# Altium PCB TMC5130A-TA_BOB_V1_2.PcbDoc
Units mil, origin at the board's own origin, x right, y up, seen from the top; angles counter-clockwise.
Board outline 1000 x 1100 mil, 4 copper layers (Top, GND, VM, Bottom), stack 27.719 mil thick; 26 components, 28 nets, 109 pads, 105 vias.
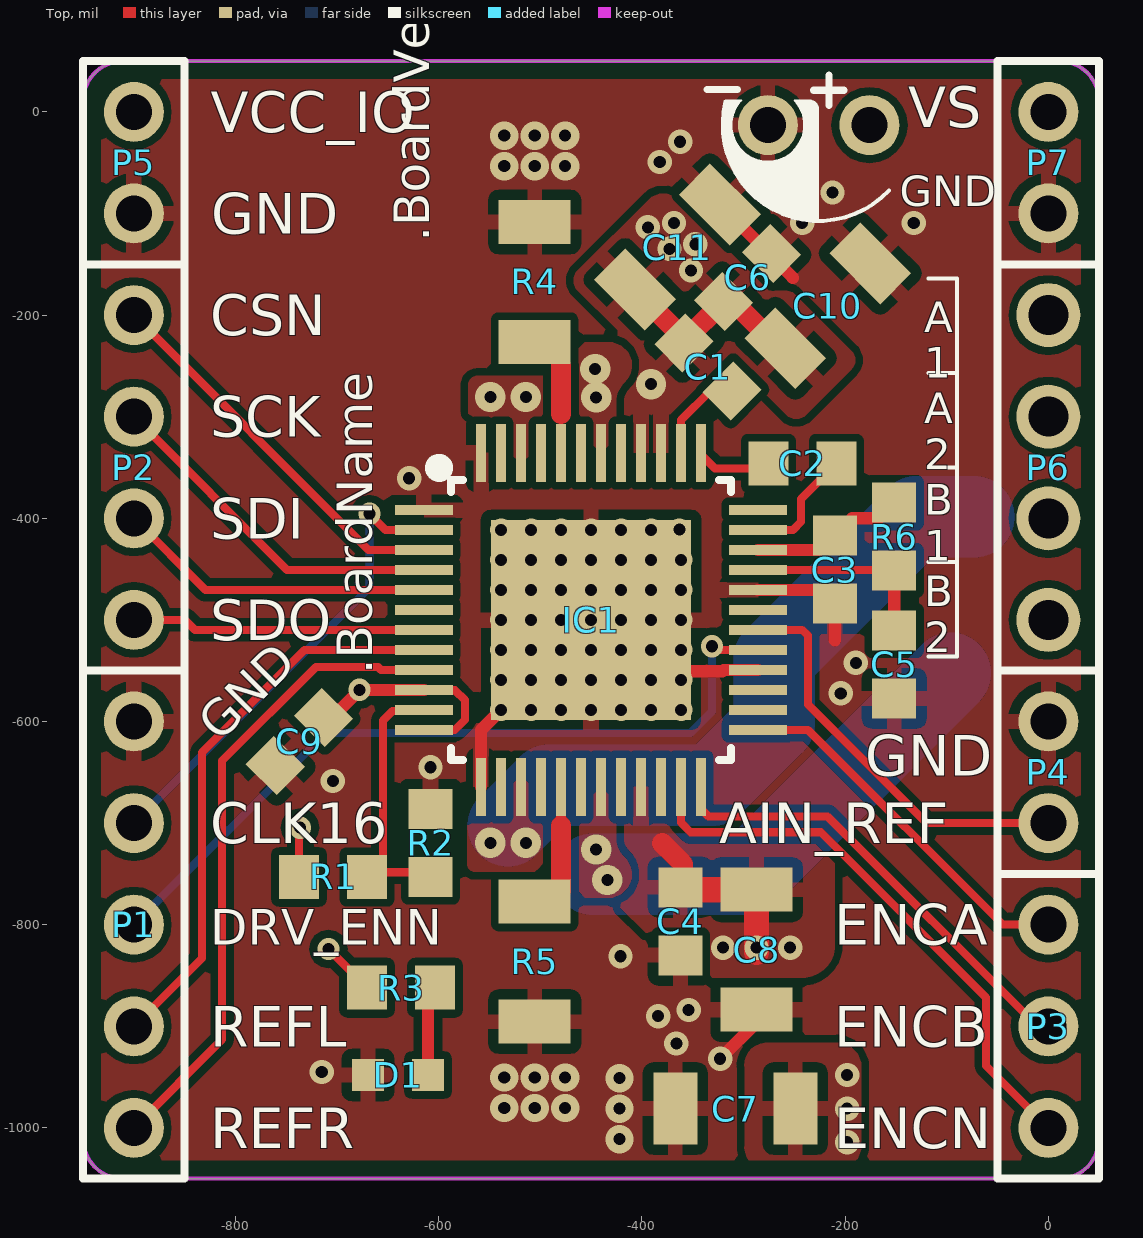
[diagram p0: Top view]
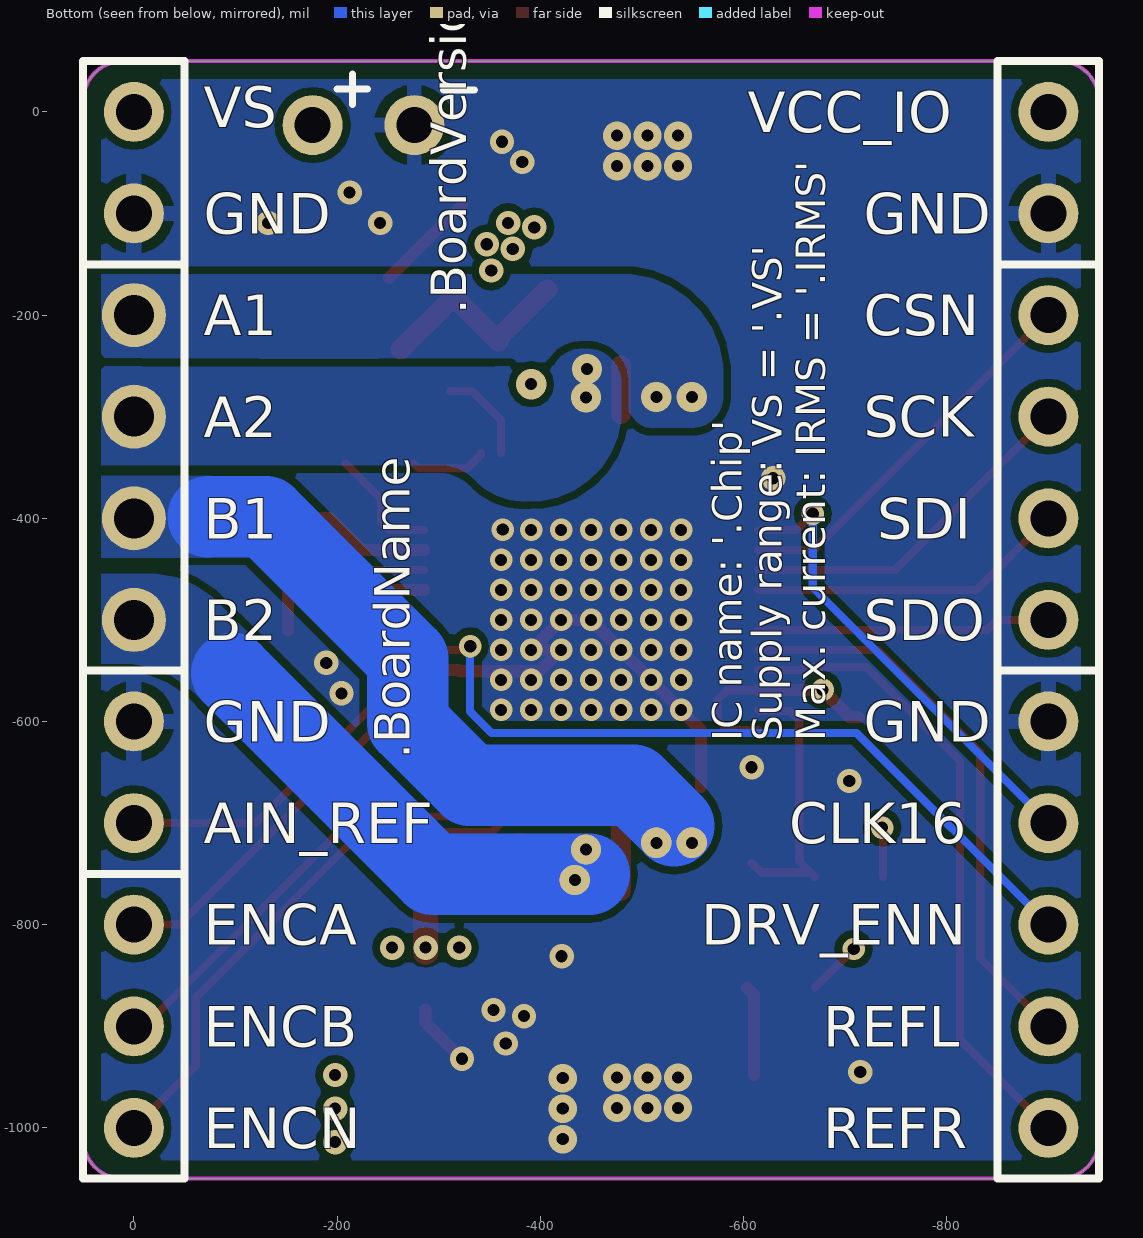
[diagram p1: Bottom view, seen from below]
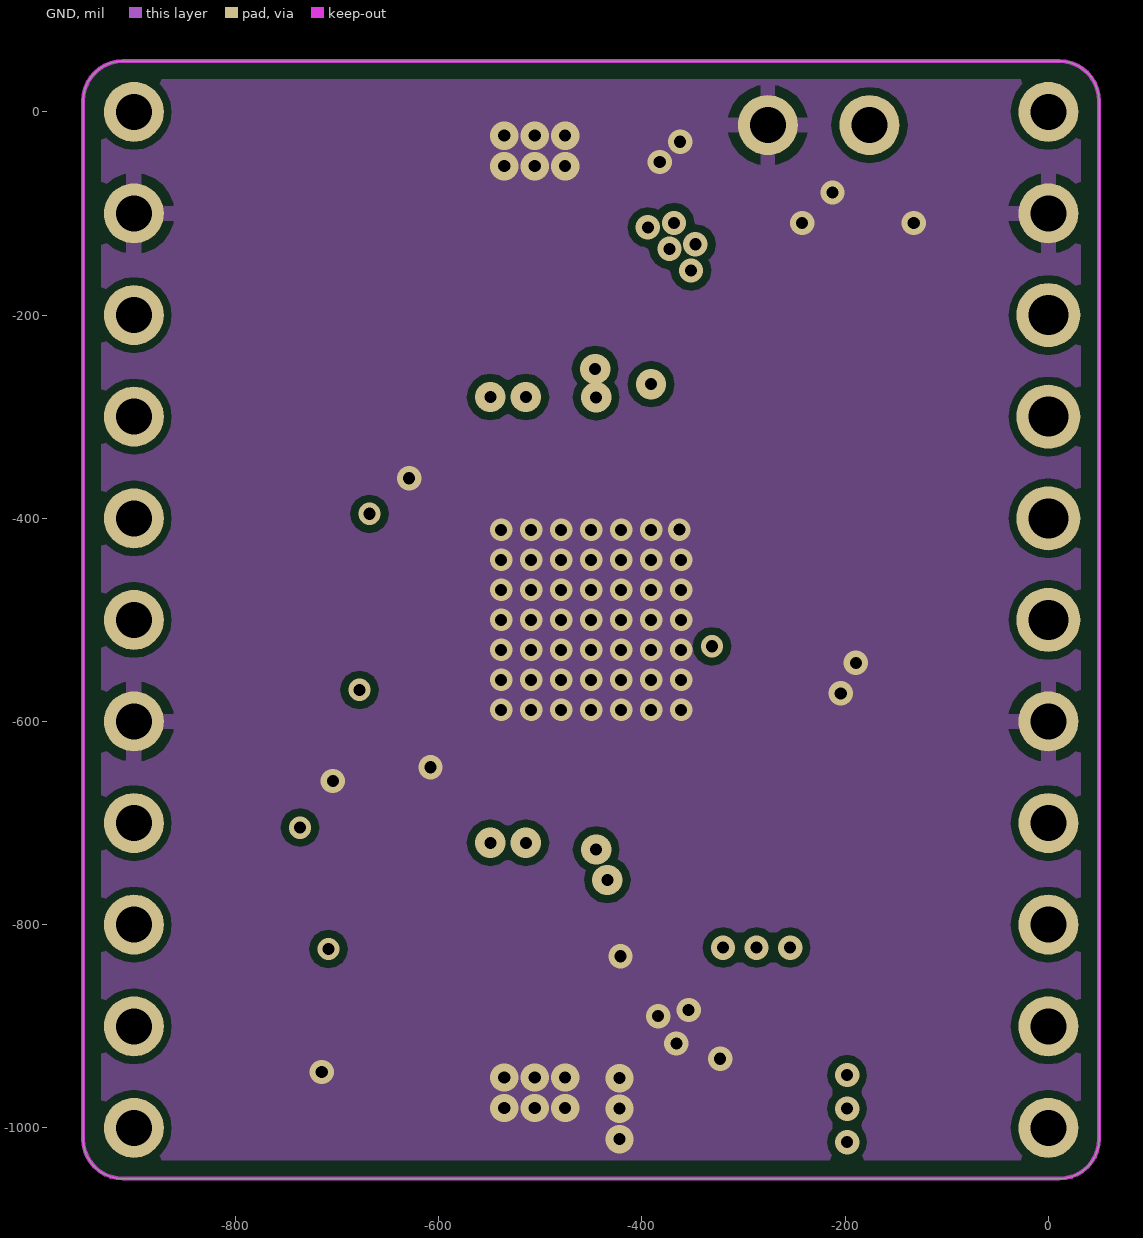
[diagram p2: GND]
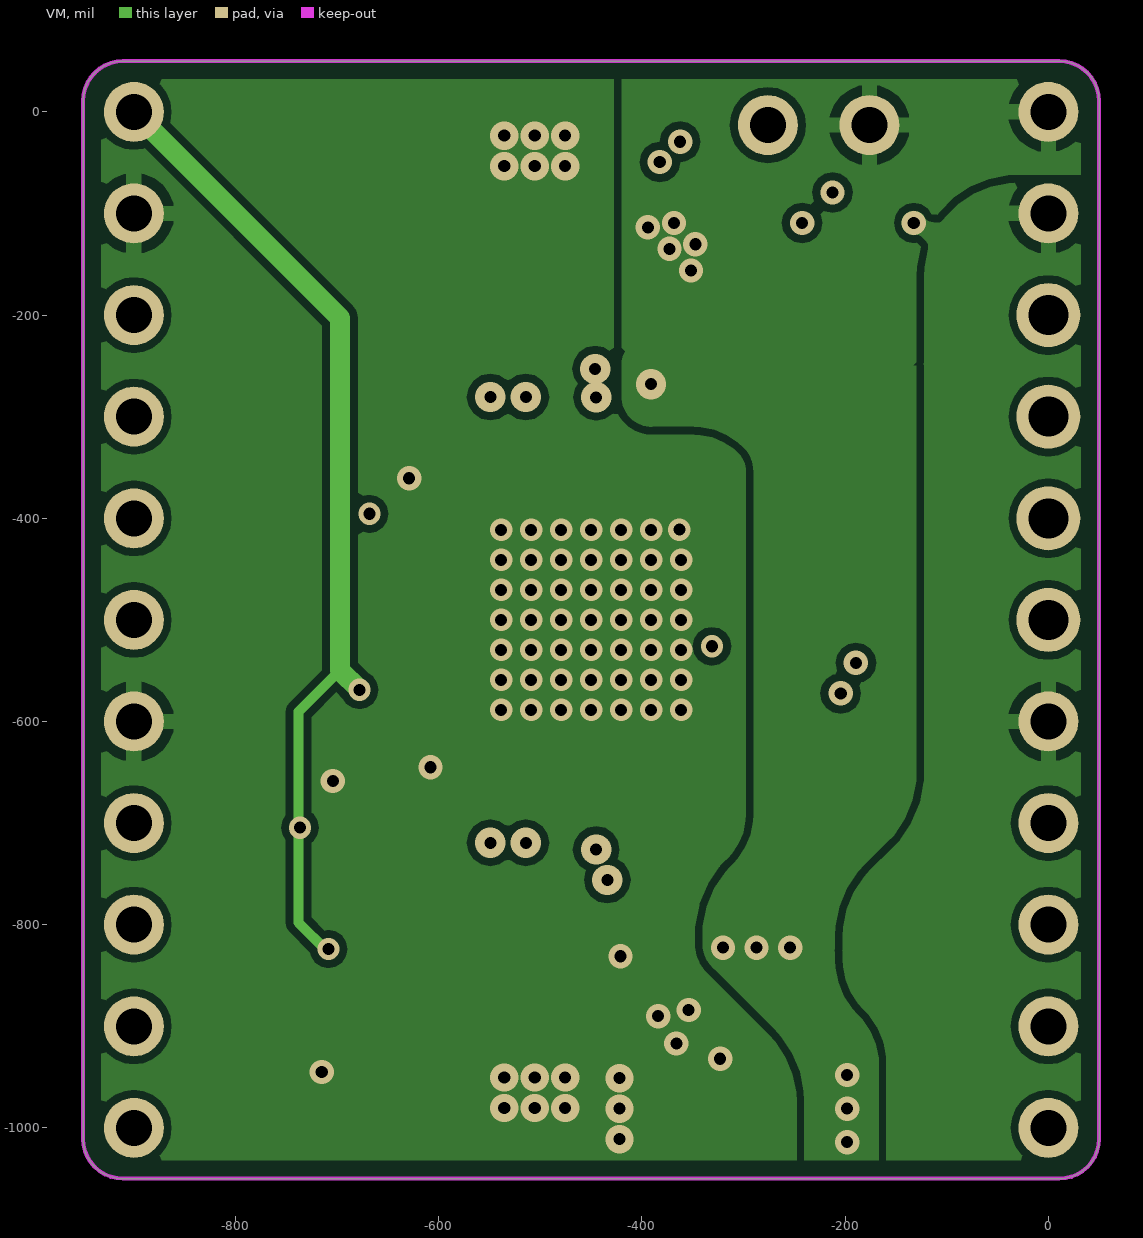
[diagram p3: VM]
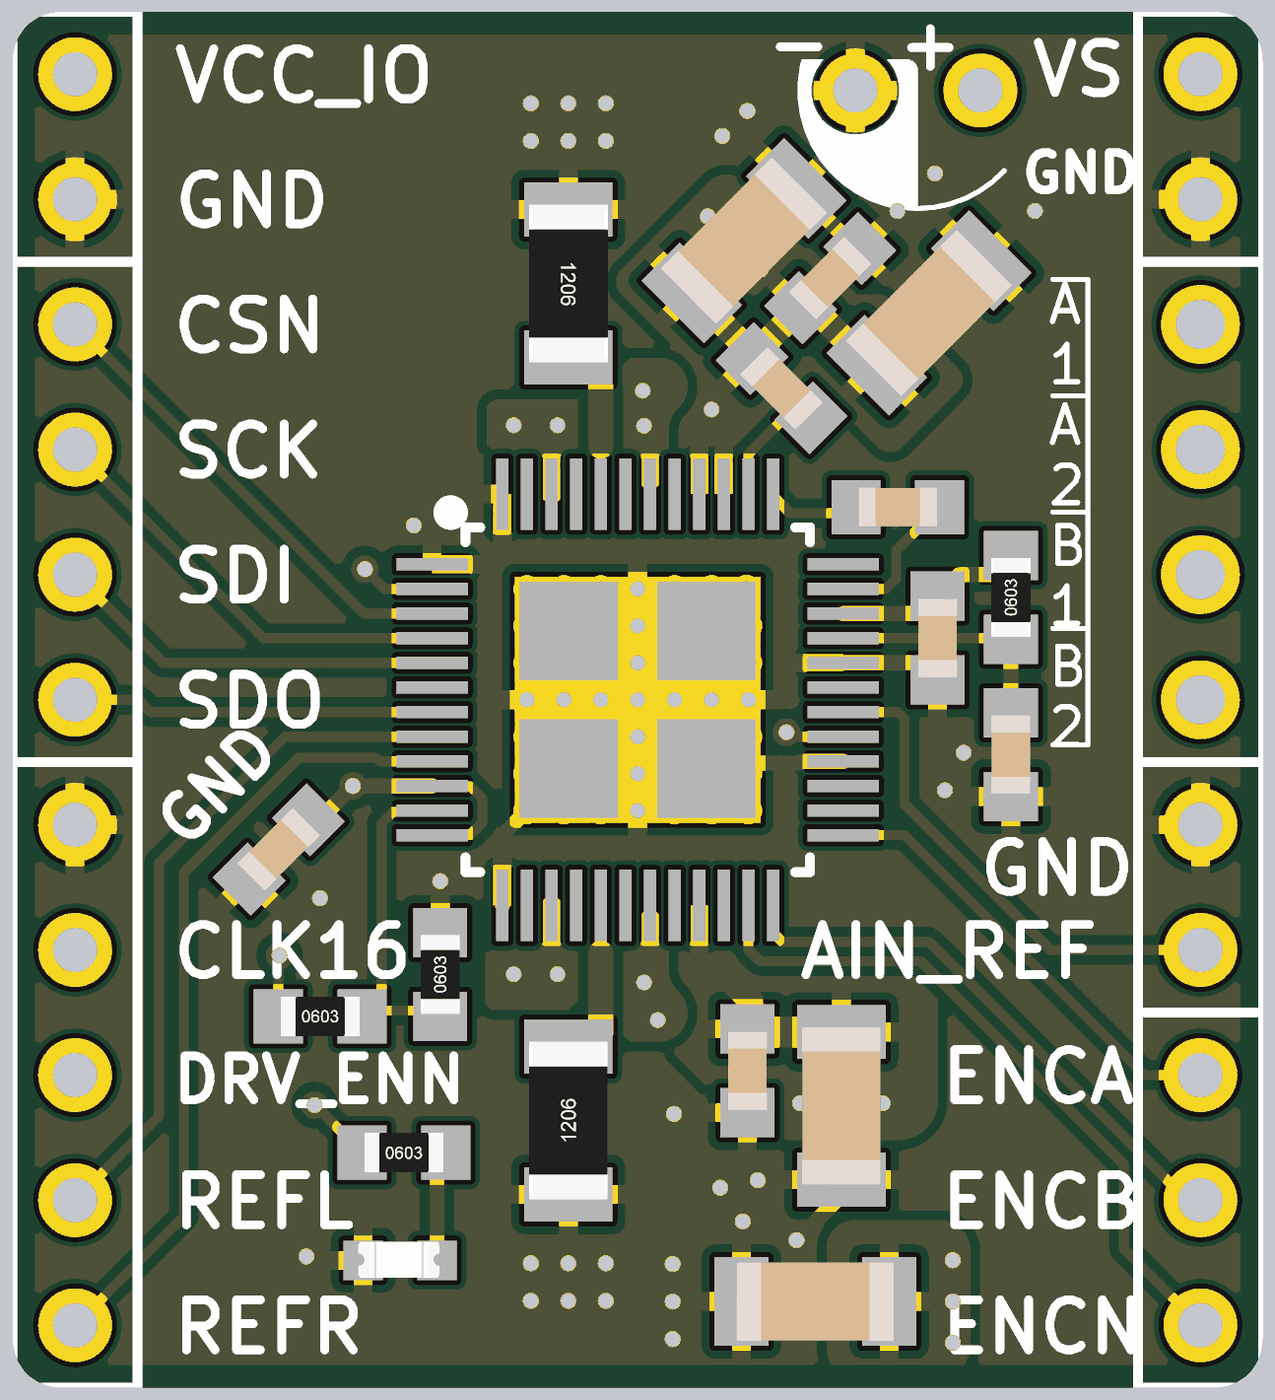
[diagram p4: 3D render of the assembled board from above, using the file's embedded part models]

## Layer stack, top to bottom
Top Solder: solder mask 0.4, Solder Resist, Dk 3.5
Top: signal copper 1.378
Dielectric 1: core 7.874, FR-4, Dk 4.8
GND: signal copper 0.689
Dielectric 2: prepreg 5, FR-4, Dk 4.2
VM: signal copper 1.4
Dielectric4: core 10, FR-4, Dk 4.2
Bottom: signal copper 1.378
Bottom Solder: solder mask 0.4, Solder Resist, Dk 3.5

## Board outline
-950,-1010.63 -950,10.63 cw(c-910.63,10.63) -910.63,50 10.63,50 cw(c10.63,10.63) 50,10.63 50,-1010.63 cw(c10.63,-1010.63) 10.63,-1050 -910.63,-1050 cw(c-910.63,-1010.63)

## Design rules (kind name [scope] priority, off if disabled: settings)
Clearance BoardOutlineClearance [OnLayer('Keep-Out Layer')] p1: gap=15.75 ignorepadtopadclearanceinfootprint=FALSE except(0: Arc-Hole Track-Hole SMDPad-Hole THPad-Hole Via-Hole Fill-Hole Poly-Hole Region-Hole Text-Hole)
Clearance "Fiducial Clearance" [HasFootprint('FIDUCIAL_40MIL')] p2: gap=26 ignorepadtopadclearanceinfootprint=FALSE except(0: Arc-Hole Track-Hole SMDPad-Hole THPad-Hole Via-Hole Fill-Hole Poly-Hole Region-Hole Text-Hole)
Clearance "Mounting Hole Clearance" [(HoleDiameter >= 110) And  IsPad  And ((PadYSize_AllLayers - HoleDiameter)  <=  1)] p3: gap=30 ignorepadtopadclearanceinfootprint=FALSE except(0: Arc-Hole Track-Hole SMDPad-Hole THPad-Hole Via-Hole Fill-Hole Poly-Hole Region-Hole Text-Hole)
Clearance [All] p4: gap=7.6 ignorepadtopadclearanceinfootprint=FALSE except(0: Arc-Hole Track-Hole SMDPad-Hole THPad-Hole Via-Hole Fill-Hole Poly-Hole Region-Hole Text-Hole)
ComponentClearance Pinheader2PinheaderClearance [InComponentClass('Pinheader') vs InComponentClass('Pinheader')] p1: gap=0 collisioncheckmode=3 verticalgap=0 showdistances=FALSE
ComponentClearance [All] p2: gap=10 collisioncheckmode=3 verticalgap=10 showdistances=FALSE
DiffPairsRouting [All] p1 off: maxlimit=10 minlimit=7.5 mostfreqgap=10 toplayer_prefgap=7.5 toplayer_minwidth=7.5 toplayer_maxwidth=7.5 toplayer_prefwidth=7.5 midlayer1_prefgap=7.5 midlayer1_minwidth=7.5 midlayer1_maxwidth=7.5 midlayer1_prefwidth=7.5 midlayer2_mingap=10 midlayer2_minwidth=15 midlayer2_maxwidth=15 midlayer2_prefwidth=15 bottomlayer_prefgap=7.5 bottomlayer_minwidth=7.5 bottomlayer_maxwidth=7.5 bottomlayer_prefwidth=7.5 maxuncoupledlength=500
HoleSize [All] p1: absolutevalues=TRUE maxlimit=100000 minlimit=11.81 maxpercent=80.000 minpercent=20.000
HoleToHoleClearance [All] p1: gap=8 allowstackedmicrovias=TRUE
MatchedLengths "SD_CARD MatchedLengths" [InNetClass('SD_CARD')] p1: tolerance=10 checknetsindiffpair=FALSE checkdiffpairvsdiffpair=TRUE checkxsignals=TRUE checkothers=TRUE
MinimumAnnularRing MinimumViaAnnualRing [All] p1: minimumring=4.92
MinimumSolderMaskSliver STM32_MinimumSolderMaskSliver [(InComponent('STM1') AND InComponent('STM2')) vs (InComponent('STM1') AND InComponent('STM2'))] p1: minsoldermaskwidth=1
MinimumSolderMaskSliver USB_HUB_MinimumSolderMaskSliver [InComponent('USB_HUB')] p2: minsoldermaskwidth=1
MinimumSolderMaskSliver [All] p3 off: minsoldermaskwidth=1.5
PasteMaskExpansion TestPadPasteMaskExpansion [HasFootprint('SMD_TP_2X2_ROUND')] p1: expansion=-78.74
PasteMaskExpansion [All] p2: expansion=0
PolygonConnect MotorpowerOutput_VM_PolygonConnect [InNetClass('MotorPowerOut')] p1: connectstyle=Direct reliefconductorwidth=70 reliefentries=4 polygonreliefangle="90 Angle" airgapwidth=10
PolygonConnect ThermalVias [IsVia] p2: connectstyle=Direct reliefconductorwidth=10 reliefentries=4 polygonreliefangle="90 Angle" airgapwidth=10
PolygonConnect MotorOutputConStyle [InNetClass('MotorOutput')] p3: connectstyle=Direct reliefconductorwidth=10 reliefentries=4 polygonreliefangle="90 Angle" airgapwidth=10
PolygonConnect [All] p4: connectstyle=Relief reliefconductorwidth=15 reliefentries=4 polygonreliefangle="90 Angle" airgapwidth=10
RoutingVias [All] p1: holewidth=12 width=22 viastyle="Through Hole" minholewidth=12 minwidth=22 maxholewidth=12 maxwidth=50
ShortCircuit [All] p1 off: allowed=FALSE
SilkToBoardRegionClearance [All] p1 off:
SilkToSilkClearance [All] p1 off: silktosilkclearance=10
SilkToSolderMaskClearance [IsPad] p1 off: minsilkscreentomaskgap=10 clearancetoexposedcopper=TRUE
SolderMaskExpansion FiducialSolderMaskExpansion [HasFootprint('FIDUCIAL_40MIL')] p1: expansion=26
SolderMaskExpansion [All] p2: expansion=4
UnRoutedNet [All] p1 off:
Width VIN_Width [InNetClass('PWR_VIN')] p1: maxlimit=300 minlimit=200 preferedwidth=210
Width Other_Width [All] p2: maxlimit=100000 minlimit=8 preferedwidth=11.81 minimp=50.000000 maximp=50.000000 favimp=50.000000
19 further rules are at their usual default settings.

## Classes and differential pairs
net class C1_Nets: +VS NetC1_2
net class C2_Nets: NetC2_1 NetC2_2
net class C3_Nets: GND VCC
net class C4_Nets: +VS GND
net class C5_Nets: 5V_OUT GND
net class C6_Nets: +VS GND
net class C7_Nets: +VS GND
net class C8_Nets: +VS GND
net class C9_Nets: GND VCC_IO
net class C10_Nets: +VS GND
net class C11_Nets: +VS GND
net class C17_Nets: +VS GND
net class D1_Nets: GND NetD1_1
net class IC1_Nets: 5V_OUT +VS AIN_REF CLK16 CSN DRV_ENN ENCA ENCB ENCN GND NetC1_2 NetC2_1 NetC2_2 NetIC1_17 NetIC1_26 NetIC1_27 NetIC1_44 OA1 OA2 OB1 OB2 REFL REFR SCK SD_MODE SDI SDO VCC VCC_IO
net class MotorPowerOut: OA1 OA2 OB1 OB2
net class P1_Nets: CLK16 DRV_ENN GND REFL REFR
net class P2_Nets: CSN SCK SDI SDO
net class P3_Nets: ENCA ENCB ENCN
net class P4_Nets: AIN_REF GND
net class P5_Nets: GND VCC_IO
net class P6_Nets: OA1 OA2 OB1 OB2
net class P7_Nets: +VS GND
net class R1_Nets: SD_MODE VCC_IO
net class R2_Nets: GND SD_MODE
net class R3_Nets: NetD1_1 VCC_IO
net class R4_Nets: GND NetIC1_44
net class R5_Nets: GND NetIC1_17
net class R6_Nets: 5V_OUT VCC

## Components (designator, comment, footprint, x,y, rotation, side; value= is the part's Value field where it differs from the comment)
C1 "100nF" C0603 -335,-251 r315 top
C2 "22nF" C0603 -242,-346 r180 top
C3 "470nF" C0603 -210.16,-450.63 r270 top
C4 "100nF" C0603 -362.16,-796.63 r270 top
C5 "4.7uF" C0603 -151.63,-543.84 r270 top
C6 "100nF" C0603 -296,-163 r45 top
C7 "10uF/35V/10%" C1206 -308,-981 r0 top
C8 "10uF/35V/10%" C1206 -287.16,-824.63 r90 top
C9 "100nF" C0603 -737.16,-619.63 r225 top
C10 "10uF/35V/10%" C1206 -217.08,-190.84 r225 top
C11 "10uF/35V/10%" C1206 -365,-133 r225 top
D1 "LED, Blue, SMD, 20mA, 2.8V, 465 nm" LED_0603 -640,-948 r180 top
IC1 "TMC5130A-TA" TMC5130_TQFP48-EP_0.5_7.0X7.0 -450,-500 r270 top
P1 "MISC" 5_PIN_THT -900,-1000 r0 top
P2 "SPI" 4_PIN_THT -900,-200 r180 top
P3 "ENC" 3_PIN_THT 0,-1000 r0 top
P4 "AIN" 2_PIN_THT 0,-700 r0 top
P5 "VCC_IO" 2_PIN_THT -900,-100 r0 top
P6 "MAB" 4_PIN_THT_1mm_hole 0,-200 r180 top
P7 "VM" 2_PIN_THT 0,-100 r0 top
R1 "0R" R0603 -704,-753 r0 top
R2 "0R" R0603 -608,-719.54 r90 top
R3 "1k" R0603 -637,-862 r0 top
R4 "0.15R / 0.5W / 1%" R1206 -505.53,-167.37 r270 top
R5 "0.15R / 0.5W / 1%" R1206 -505.53,-836.37 r90 top
R6 "2R2/1%/" R0603 -151.63,-418.17 r90 top

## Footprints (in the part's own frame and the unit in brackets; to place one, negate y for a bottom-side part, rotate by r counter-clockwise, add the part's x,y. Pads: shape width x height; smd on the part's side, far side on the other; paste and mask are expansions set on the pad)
2_PIN_THT [mm]
  round 1.5 hole 0.9: 1(0,0) 2(0,2.54)
  silkscreen extent -1.27,-1.27 1.27,3.81
3_PIN_THT [mm]
  round 1.5 hole 0.9: 1(0,0) 2(0,2.54) 3(0,5.08)
  silkscreen extent -1.27,-1.27 1.27,6.35
4_PIN_THT [mm]
  round 1.5 hole 0.9: 1(0,0) 2(0,2.54) 3(0,5.08) 4(0,7.62)
  silkscreen extent -1.27,-1.27 1.27,8.89
4_PIN_THT_1mm_hole [mm]
  round 1.6 hole 1: 1(0,0) 2(0,2.54) 3(0,5.08) 4(0,7.62)
  silkscreen extent -1.27,-1.27 1.27,8.89
5_PIN_THT [mm]
  round 1.5 hole 0.9: 1(0,0) 2(0,2.54) 3(0,5.08) 4(0,7.62) 5(0,10.16)
  silkscreen extent -1.27,-1.27 1.27,11.43
C0603 [mm] "0603 ceramic capacitor"
  rect 1x1.1 smd: 1(-0.85,0) 2(0.85,0)
  body extent -0.8,-0.4 0.8,0.4, height 0.8
C1206 [mm] "1206 ceramic capacitor"
  rect 1.1x1.8 smd: 1(-1.5,0) 2(1.5,0)
  body extent -1.6,-0.8 1.6,0.8, height 0.76
LED_0603 [mm]
  rect 0.8x0.8 smd: 1(-0.75,0) 2(0.75,0)
  body extent -0.8,-0.38 0.85,0.35, height 0.68
R0603 [mm] "0603 resistor"
  rect 1x1.1 smd: 1(-0.85,0) 2(0.85,0)
  body extent -0.8,-0.4 0.8,0.4, height 0.45
R1206 [mm] "1206 resistor"
  rect 1.1x1.8 smd: 1(-1.5,0) 2(1.5,0)
  body extent -1.6,-0.8 1.6,0.8, height 0.6
TMC5130_TQFP48-EP_0.5_7.0X7.0 [mm]
  rect 0.25x1.45 smd: 1(-2.75,-4.175) 2(-2.25,-4.175) 3(-1.75,-4.175) 4(-1.25,-4.175) 5(-0.75,-4.175) 6(-0.25,-4.175) 7(0.25,-4.175) 8(0.75,-4.175) 9(1.25,-4.175) 10(1.75,-4.175) 11(2.25,-4.175) 12(2.75,-4.175) 25(2.75,4.175) 26(2.25,4.175) 27(1.75,4.175) 28(1.25,4.175) 29(0.75,4.175) 30(0.25,4.175) 31(-0.25,4.175) 32(-0.75,4.175) 33(-1.25,4.175) 34(-1.75,4.175) 35(-2.25,4.175) 36(-2.75,4.175)
  rect 1.45x0.25 smd: 13(4.175,-2.75) 14(4.175,-2.25) 15(4.175,-1.75) 16(4.175,-1.25) 17(4.175,-0.75) 18(4.175,-0.25) 19(4.175,0.25) 20(4.175,0.75) 21(4.175,1.25) 22(4.175,1.75) 23(4.175,2.25) 24(4.175,2.75) 37(-4.175,2.75) 38(-4.175,2.25) 39(-4.175,1.75) 40(-4.175,1.25) 41(-4.175,0.75) 42(-4.175,0.25) 43(-4.175,-0.25) 44(-4.175,-0.75) 45(-4.175,-1.25) 46(-4.175,-1.75) 47(-4.175,-2.25) 48(-4.175,-2.75)
  rrect0% 5x5 smd paste-254: 49(0,0)
  silkscreen extent -3.9,-3.9 3.5,3.5, body extent -3.5,-3.5 3.5,3.5, height 1

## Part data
C1: library part Capacitor, "Ceramic capacitor", MPN=MC0603F104M500CT, Voltage rating=50V
C2: library part Capacitor, "Ceramic capacitor", MPN=MC0603B223K500CT, Voltage rating=50V
C3: library part Capacitor, "Ceramic capacitor", MPN=MC0603X474K160CT, Voltage rating=16V
C4 C6 C9: library part Capacitor, "Ceramic capacitor", Manufacturer=Multicomp, MPN=MC0603F104M500CT, Voltage rating=50V
C5: library part Capacitor, "Ceramic capacitor", MPN=MC0603X475K100CT, Voltage rating=10V
C7 C8 C10 C11: library part Capacitor, "Ceramic capacitor", Capacitance=10uF, MPN=GRM31CC8YA106KA12L, VoltageRating=35V
D1: Colour=Blue, Current rating=20mA, MPN=LTST-C191TBKT-5A
IC1: "High voltage(up to 46V) controller for two-phase bipolar stepper motor, with SPI, Step/Dir, UART, TQFP48-EP(7x7)", Manufacturer=TRINAMIC
P1: library part "Header 5", "Header, 5-Pin"
P2: library part "Header 4", "Header, 4-Pin"
P3: library part "Header 3", "Header, 3-Pin"
P4 P5 P7: library part "Header 2", "Header, 2-Pin"
P6: library part "Wire-To-Board Connector, 2.5 mm, 4 Contacts, Header, EH Series, Through Hole, 1 Rows", "Wire-To-Board Connector, 2.5 mm, 4 Contacts, Header, EH Series, Through Hole, 1 Rows", MPN=B4B-EH-A
R1 R2: library part "0 ohm, 0603 [1608 Metric], 100 mW, MCWR Series", "SMD Chip Resistor, Thick Film, 0 ohm, 0603 [1608 Metric], 100 mW, MCWR Series", MPN="MCWR06X000 PTL", PowerRating=100mW, Temp coefficient=*ppm
R3: library part "1 kohm, 50 V, 0603 [1608 Metric], 63 mW, ± 1%, MC Series", "1 kohm, 50 V, 0603 [1608 Metric], 63 mW, ± 1%, MC Series", MPN=MC0063W060311K, PowerRating=63mW, Temp coefficient=*ppm, VoltageRating=50V
R4 R5: library part "0.15 Ohm ±1% 0.5W, 1/2W Chip Resistor 1206 (3216 Metric) Automotive AEC-Q200, Current Sense Thick Film", "0.15 Ohm ±1% 0.5W, 1/2W Chip Resistor 1206 (3216 Metric) Automotive AEC-Q200, Current Sense Thick Film", MPN=ERJ-8BSFR15V, PowerRating=0.5W, Resistance=0.15R, Temp coefficient=*ppm
R6: library part Resistor, "Resistor", MPN=MC0063W060312R2, Power rating=*mW, Resistance=2R2, Temp coefficient=*ppm, Voltage rating=*V

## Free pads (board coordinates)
  round 59.06 hole 35.43: 1(-176,-13) 2(-276,-13)

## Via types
v1: diameter 22, hole 12, Top to Bottom, tented both sides, 54 vias
v2: diameter 24, hole 12, Top to Bottom, tented both sides, 27 vias
v3: diameter 28, hole 12, Top to Bottom, tented both sides, 15 vias
v4: diameter 29.81, hole 11.81, Top to Bottom, tented both sides, 9 vias

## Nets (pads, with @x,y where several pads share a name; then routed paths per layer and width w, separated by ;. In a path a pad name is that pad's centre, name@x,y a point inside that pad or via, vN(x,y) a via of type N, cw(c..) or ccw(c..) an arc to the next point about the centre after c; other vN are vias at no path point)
5V_OUT: C5.1 IC1.33 R6.1 | length 180.4
  Top w8: IC1.33 R6.1@-164,-450.79
  Top w12: C5.1 R6.1
+VS: C1.1 C4.1 C6.1 C7.2 C8.2 C10.2 C11.2 IC1.21 IC1.39 IC1.40 P7.2 pad.1 | length 393.2
  Top w8: v2(-287.16,-822.52) v2@-286.16,-822.52
  Top w12: C1.1 -358.66,-225.66 C1.1@-358.66,-222.85
  Top w20: C11.2 C1.1@-358.66,-222.85 ; -380,-720 -359.75,-740.25 C4.1@-359.75,-765.57 ; C1.1@-358.66,-225.66 C6.1 -309.85,-186.66 C10.2@-262.76,-233.76
  Top w25: C4.1@-359.75,-765.57 C8.2 v2@-287.16,-827.16
  other v2: -198.06,-1014 -198.06,-981 -198.06,-948 -320.16,-822.52 -254.16,-822.52 -351.65,-156.08 -372.87,-134.87 -347.34,-130.34 -394.08,-113.65 -368.34,-109.34
  other v4: -391,-268
AIN_REF: IC1.30 P4.1 | length 404.2
  Top w8: IC1.30 -242.15,-509.84 -236.62,-515.38 -236.62,-583.38 -120,-700 P4.1
CLK16: IC1.2 P1.4 | length 460.7
  Top w8: v1(-668.16,-395.63) -652.37,-411.42 IC1.2
  Bottom w8: P1.4 -668.16,-468.16 v1(-668.16,-395.63)
CSN: IC1.3 P2.1 | length 381.4
  Top w8: P2.1 -668.9,-431.1 IC1.3
DRV_ENN: IC1.29 P1.3 | length 767.4
  Top w8: v1(-331,-526) ccw(c-327.47,-526) -327.47,-529.53 IC1.29
  Bottom w8: P1.3 -711.18,-611.18 -352.06,-611.18 -331,-590.13 v1(-331,-526)
ENCA: IC1.25 P3.3 | length 365
  Top w8: IC1.25 -236.52,-608.27 -44.79,-800 P3.3
ENCB: IC1.24 P3.2 | length 452.2
  Top w8: IC1.24 -341.73,-686.27 -334.6,-693.4 -217.33,-693.4 -10.73,-900 P3.2
ENCN: IC1.23 P3.1 | length 560.4
  Top w8: IC1.23 -361.42,-699.58 -352,-709 -223.79,-709 -61.16,-871.63 -61.16,-938.84 P3.1
GND: C3.2 C4.2 C5.2 C6.2 C7.1 C8.1 C9.2 C10.1 C11.1 D1.2 IC1.1 IC1.13 IC1.28 IC1.32 IC1.48 IC1.49 P1.5 P4.2 P5.1 P7.1 pad.2 R2.2 R4.1 R5.1 | length 736.4
  Top w12: IC1.13 -558.27,-608.27 v1(-538.58,-588.58) v1(-509.06,-559.06) v1(-479.53,-529.53) v1(-450,-500) v1(-420.47,-500) v1(-390.94,-529.53) v1(-420.47,-529.53) -399.4,-550.6 -320.81,-550.6 -319.42,-549.21 IC1.28 ; C11.1 -251.43,-163.05 -251.43,-163.47 ; v2(-323,-932) -287.16,-896.16 C8.1 ; IC1.32 -223.78,-470.47 C3.2 -210.16,-519.84 -210,-520
  other v1: -509.06,-588.58 -479.53,-588.58 -450,-588.58 -420.47,-588.58 -390.94,-588.58 -361.42,-588.58 -538.58,-559.06 -479.53,-559.06 -450,-559.06 -420.47,-559.06 -390.94,-559.06 -361.42,-559.06 -538.58,-529.53 -509.06,-529.53 -450,-529.53 -361.42,-529.53 -538.58,-500 -509.06,-500 -479.53,-500 -390.94,-500 -361.42,-500 -538.58,-470.47 -509.06,-470.47 -479.53,-470.47 -450,-470.47 -420.47,-470.47 -390.94,-470.47 -361.42,-470.47 -538.58,-440.94 -509.06,-440.94 -479.53,-440.94 -450,-440.94 -420.47,-440.94 -390.94,-440.94 -361.42,-440.94 -538.58,-411.42 -509.06,-411.42 -479.53,-411.42 -450,-411.42 -420.47,-411.42 -390.94,-411.42 -363.11,-411.17
  other v2: -715,-945 -366,-917 -384,-890 -354,-884 -421,-831 -704.16,-658.63 -608,-645 -204.34,-572.34 -189.34,-542.34 -629.16,-360.63 -242.34,-109.34 -132.34,-109.34 -212.34,-79.34 -382.34,-49.34 -362.34,-29.34
  other v3: -422.06,-1011 -535.53,-980.43 -505.53,-980.43 -475.53,-980.43 -422.06,-981 -535.53,-950.43 -505.53,-950.43 -475.53,-950.43 -422.06,-951 -535.53,-53.32 -505.53,-53.32 -475.53,-53.32 -535.53,-23.32 -505.53,-23.32 -475.53,-23.32
NetC1_2: C1.2 IC1.38 | length 94.2
  Top w8: IC1.38 -361.42,-303.42 -332.66,-274.66 C1.2
NetC2_1: C2.1 IC1.35 | length 117.4
  Top w8: IC1.35 -251.42,-411.42 -243.41,-403.41 -243.41,-380.88 C2.1
NetC2_2: C2.2 IC1.37 | length 75.7
  Top w8: IC1.37 -341.73,-337.27 -328,-351 -280.46,-351 C2.2
NetD1_1: D1.1 R3.2 | length 88.9
  Top w12: D1.1 -610.47,-868.94 R3.2
NetIC1_17: IC1.17 R5.2 | length 100.2
  Top w10: -479.53,-700.78 IC1.17
  Top w20: R5.2@-479.53,-766.47 -479.53,-702.68
NetIC1_44: IC1.44 R4.2 | length 47.4
  Top w20: -479.53,-297.37 -479.53,-250
OA1: IC1.46 P6.1
  other v4: -549.21,-280.63 -514.21,-280.63
OA2: IC1.42 P6.2
  other v4: -445,-281 -446,-253
OB1: IC1.15 P6.3 | length 621.7
  Bottom w80: -531.71,-702.73 -491.76,-662.78 -330.68,-662.78 -269.6,-601.7 -269.6,-538.31 -129.66,-398.37 -73.21,-398.37
  other v4: -549.21,-719.37 -514.21,-719.37
OB2: IC1.19 P6.4 | length 434
  Bottom w80: -448.21,-750.38 -294.23,-750.38 -96.21,-552.37
  other v4: -434,-756 -445,-726
REFL: IC1.8 P1.2 | length 557.8
  Top w8: P1.2 -833.03,-833.03 -833.03,-630.4 -732.16,-529.53 IC1.8
REFR: IC1.9 P1.1 | length 635.6
  Top w8: P1.1 -813.16,-913.16 -813.16,-638.63 -720.83,-546.3 -659.54,-546.3 -656.63,-549.21 IC1.9
SCK: IC1.4 P2.2 | length 348.1
  Top w8: P2.2 -749.21,-450.79 IC1.4
SD_MODE: IC1.11 R1.2 R2.1 | length 267
  Top w8: R1.2 R1.2@-665.9,-748.36 ; IC1.11 -615.29,-589.5 -645.48,-589.5 -654.85,-598.88 -654.85,-737.31 R1.2@-665.9,-748.36 ; R2.1@-608,-739.28 -617.08,-748.36 R1.2@-665.9,-748.36
SDI: IC1.5 P2.3 | length 314.8
  Top w8: P2.3 -829.53,-470.47 IC1.5
SDO: IC1.7 P2.4 | length 289.7
  Top w8: P2.4 -849.63,-500 -839.79,-509.84 IC1.7
VCC: C3.1 IC1.34 R6.2 | length 153.2
  Top w12: IC1.34 -224.09,-431.1 C3.1 -192.99,-400 -166.93,-400 R6.2
VCC_IO: C9.1 IC1.10 IC1.12 P5.2 R1.1 R3.1 | length 1286.3
  Top w8: R1.1 -737.46,-705.46 v1(-736.46,-704.46) ; v1(-708.46,-824) R3.1 ; IC1.12 -584.19,-608.27 -574.23,-598.31 -574.23,-578.86 -583.77,-569.31 -613.96,-569.31 IC1.10
  Top w12: C9.1 -704.76,-595.97 v1@-677.79,-569 ; v1@-677.69,-568.9 IC1.10
  VM w10: v1@-710.23,-825.77 -738,-798 -738,-590.47 -697.16,-549.63
  VM w20: P5.2 -697.16,-202.84 -697.16,-549.63 v1(-677.89,-568.9)
pads on no net: IC1.6 IC1.14 IC1.16 IC1.18 IC1.20 IC1.22 IC1.26 IC1.27 IC1.31 IC1.36 IC1.41 IC1.43 IC1.45 IC1.47

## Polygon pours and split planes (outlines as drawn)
OA1 on Top "OA1" (solid, pour order 11): -518.9,-342.52 ccw(c-518.9,-332.68) -509.06,-332.68 -509.06,-307.09 cw(c-505.12,-307.09) -505.12,-303.15 -497.25,-303.15 ccw(c-497.25,-299.22) -493.31,-299.22 -493.31,-295.28 -493.31,-263.78 ccw(c-497.25,-263.78) -497.25,-259.85 -561.76,-259.85 ccw(c-561.76,-268.93) -570.84,-268.93 -570.84,-295.28 ccw(c-562.07,-294.38) -561.17,-303.15 -536.62,-303.15 -532.68,-303.15 cw(c-532.68,-307.09) -528.74,-307.09 -528.74,-332.68 ccw(c-518.9,-332.68)
OB1 on Top "OB1" (solid, pour order 10): -518.9,-657.48 cw(c-518.9,-667.33) -509.06,-667.33 -509.06,-692.92 ccw(c-505.12,-692.92) -505.12,-696.85 -497.25,-696.85 cw(c-497.25,-700.79) -493.31,-700.79 -493.31,-724.41 cw(c-521.83,-724.41) -501.66,-744.58 -505.12,-748.03 -540.56,-748.03 -564.18,-748.03 cw(c-564.18,-740.16) -572.05,-740.16 -572.05,-704.73 cw(c-564.18,-704.73) -564.18,-696.85 -532.72,-696.85 -532.72,-696.61 -532.44,-696.61 ccw(c-532.44,-692.92) -528.74,-692.92 -528.74,-667.33 cw(c-518.9,-667.33) -518.9,-657.48
OA2 on Top "TOP_OA2" (solid, pour order 12): -440.16,-335.63 -455.91,-319.88 -455.91,-312.99 -479.53,-289.37 -479.53,-250 -456.16,-226.63 -443.16,-226.63 -433.16,-226.63 cw(c-433.16,-249.63) -410.16,-249.63 cw(c-434.3,-249.63) -417.23,-266.7 -418.16,-267.63 ccw(c-401.26,-284.53) -425.16,-284.53 -425.16,-285.63 -425.16,-320.63 -440.16,-335.63
OB2 on Top "TOP_OA2" (solid, pour order 13): -440.16,-664.37 -455.91,-680.12 -455.91,-687.01 -479.53,-710.63 -479.53,-750 -456.16,-773.37 -443.16,-773.37 -433.16,-773.37 ccw(c-433.16,-750.37) -410.16,-750.37 ccw(c-434.3,-750.37) -417.23,-733.3 -418.16,-732.37 cw(c-401.26,-715.47) -425.16,-715.47 -425.16,-714.37 -425.16,-679.37 -440.16,-664.37
GND on Top "TOP_GND" (solid, pour order 19): -950,-1010.63 ccw(c-910.63,-1010.63) -910.63,-1050 10.63,-1050 ccw(c10.63,-1010.63) 50,-1010.63 50,10.63 ccw(c10.63,10.63) 10.63,50 -910.63,50 ccw(c-910.63,10.63) -950,10.63
+VS on Top "TOP_VM" (solid, pour order 14): -420.47,-664.37 -445,-688.9 -445,-719 -445,-759.19 -401.16,-803.04 -352.16,-852.03 -241.72,-852.03 ccw(c-241.72,-820.31) -210,-820.31 -210,-800 -210,-739.51 -212.06,-737.46 -239.48,-710.03 -334.33,-710.03 -335.44,-710.03 -381.1,-664.37
+VS on Top "+VS_L01_P006" (solid, pour order 6): -274.94,-1041 -208.95,-1041 ccw(c-208.94,-1016) -183.94,-1016 -183.94,-941 ccw(c-208.94,-941) -208.95,-916 -276.57,-916 ccw(c-276.58,-938.51) -298.94,-941 -298.95,-1017 ccw(c-276.55,-1018.6)
+VS on Top "+VS_L01_P015" (solid, pour order 15): -424,-336.63 -424,-215 -463,-176 cw(c-453,-166) -463,-156 -393.25,-86.25 cw(c-379,-100.5) -364.75,-86.25 -274.99,-176.01 -252.99,-176.01 -194,-235 cw(c-203.49,-244.5) -194,-254 -238,-298 cw(c-248,-288) -258,-298 -298,-258 -316,-258 -359.42,-301.42 -359.42,-336.63
GND on GND "TOP_GND" (solid, pour order 18): -950,-1010.63 ccw(c-910.63,-1010.63) -910.63,-1050 10.63,-1050 ccw(c10.63,-1010.63) 50,-1010.63 50,10.63 ccw(c10.63,10.63) 10.63,50 -910.63,50 ccw(c-910.63,10.63) -950,10.63
GND on Bottom "TOP_GND" (solid, pour order 17): -950,-1010.63 ccw(c-910.63,-1010.63) -910.63,-1050 10.63,-1050 ccw(c10.63,-1010.63) 50,-1010.63 50,10.63 ccw(c10.63,10.63) 10.63,50 -910.63,50 ccw(c-910.63,10.63) -950,10.63
OA2 on Bottom "OA2_L04_P000" (solid, pour order 0): -446,-233.01 ccw(c-446.01,-266.52) -479.52,-266.52 -479.52,-294.48 ccw(c-391,-294.48) -391,-383 ccw(c-385.09,-313.04) -339.8,-366.69 cw(c-300.6,-397.54) -306.5,-348 50,-348 50,-249.77 cw(c-181.85,24817.03) -413.71,-249.77 ccw(c-440.41,-263.13) -437.42,-233.43 ccw(c-445.79,-315.62)
OA1 on Bottom "OA1_L04_P003" (solid, pour order 3): -482.15,-246.34 -482.15,-273.98 cw(c-526.01,-273.99) -495,-305 cw(c-509.48,-290.52) -509.49,-311 -549,-311 cw(c-549,-280) -580,-280 -580,-259.57 cw(c-480,-259.57) -480,-159.57 -58,-159.57 50,-159.57 50,-246.34 -18,-246.34
OB1 on Bottom "OB1_L04_P004" (solid, pour order 4): -77.21,-358.37 -77.21,-438.65 50,-438.65 50,-358.37
OB2 on Bottom "OB2_L04_P002" (solid, pour order 2): -143.21,-543.37 -83.5,-483.66 cw(c-12.79,-554.37) -12.79,-454.37 49.79,-454.37 49.79,-543.16 50,-543.37 10.21,-543.37 ccw(c10.21,-643.37) -60.5,-572.66 -87.21,-599.37
GND on VM "TOP_GND" (solid, pour order 16): -950,-1010.63 ccw(c-910.63,-1010.63) -910.63,-1050 10.63,-1050 ccw(c10.63,-1010.63) 50,-1010.63 50,10.63 ccw(c10.63,10.63) 10.63,50 -910.63,50 ccw(c-910.63,10.63) -950,10.63
+VS on VM "VM_VM" (solid, pour order 9): -130,-250 -251.6,-250 cw(c-251.6,-223.54) -270.3,-242.25 ccw(c-324.02,-295.97) -324.02,-220 -370,-220 -390,-220 ccw(c-390,-250) -420,-250 -420,-280 ccw(c-390,-280) -390,-310 -348.28,-310 cw(c-348.28,-378.28) -300,-330 cw(c-324.14,-354.14) -290,-354.14 -290,-670 -290,-691.72 cw(c-358.28,-691.72) -310,-740 -310.71,-740.71 ccw(c-240,-811.42) -340,-811.42 -340,-820 ccw(c-310,-820) -310,-850 -300,-850 -240,-850 ccw(c-240,-820) -210,-820 -210,-811.42 cw(c-110,-811.42) -180.71,-740.71 -180,-740 -159.29,-719.29 ccw(c-230,-648.58) -130,-648.58 -130,-450
+VS on VM "+VS_L03_P008" (solid, pour order 8): -333.3,-839.12 -269.29,-903.14 cw(c-340,-973.85) -240,-973.85 -240,-1050 -167,-1050 -167,-938.7 ccw(c-238.7,-938.7) -188,-888 cw(c-134.89,-834.89) -210,-834.89 -210,-822.95
+VS on VM "+VS_L03_P005" (solid, pour order 5): -130,-250 -130,-162 cw(c-30,-162) -30,-62 50,-62 50,50 -419.75,50 -419.75,-232.25 -403,-249
no net on Top Overlay "NONET_L-01_P-001" (solid, pour order 7): -321,-13 ccw(c-227,-13) -227,-107 -226,-107 -226,3 ccw(c-235,3) -235,12 -306,12 -312,12 -317,12 -317.4,10.63 ccw(c-317.31,9.87) -318.07,9.96

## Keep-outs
Keep-Out Layer:
  the board outline again, w4

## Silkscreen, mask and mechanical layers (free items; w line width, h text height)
Top Overlay:
  pour cut-out: -276,22 -279.45,22 -286.21,20.65 -292.58,18.02 -298.31,14.19 -303.19,9.31 -307.02,3.58 -309.65,-2.79 -311,-9.55 -311,-13 -311,-16.45 -309.65,-23.21 -307.02,-29.58 -303.19,-35.31 -298.31,-40.19 -292.58,-44.02 -286.21,-46.65 -279.45,-48 -276,-48 -272.55,-48 -265.79,-46.65 -259.42,-44.02 -253.69,-40.19 -248.81,-35.31 -244.98,-29.58 -242.35,-23.21 -241,-16.45 -241,-13 -241,-9.55 -242.35,-2.79 -244.98,3.58 -248.81,9.31 -253.69,14.19 -259.42,18.02 -265.79,20.65 -272.55,22 -276,22
  lines w4: -317.46,10.12 ccw(c-226,-13) -156.87,-77.19 ; -118,-536 -90,-536 -90,-164 -118,-164 ; -118,-443 -90,-443 ; -118,-350 -90,-350 ; -118,-257 -90,-257
  lines w7: -336,22 -306,22 ; -231,21.33 -201,21.33 ; -216,6.33 -216,36.33
  text "VS" at -138.01,-15 h40
  text "VCC_IO" at -824.16,-19.99 h40
  text "GND" at -146,-93 h30
  text "GND" at -824,-119.99 h40
  text ".BoardVersion" at -609.34,-127.89 h35 r90
  text "CSN" at -825,-219.99 h40
  text "SCK" at -825,-319.99 h40
  text "SDI" at -825,-419.99 h40
  text "SDO" at -825,-519.99 h40
  text "A / 1 / A / 2 / B / 1 / B / 2" at -122,-531.67 h30
  text ".BoardName" at -665.4,-553.58 h35 r90
  text "GND" at -815.53,-621.37 h35 r45
  text "GND" at -180.16,-653.62 h40
  text "CLK16" at -825,-719.99 h40
  text "AIN_REF" at -323.92,-719.99 h40
  text "DRV_ENN" at -825,-819.99 h35
  text "ENCA" at -210.62,-819.99 h40
  text "REFL" at -825,-919.99 h40
  text "ENCB" at -210.62,-919.99 h40
  text "REFR" at -825,-1019.99 h40
  text "ENCN" at -210.62,-1019.99 h40
Bottom Overlay:
  lines w7: -335,21.66 -305,21.66 ; -230,22.34 -200,22.34 ; -215,7.34 -215,37.34
  text "VS" at -69,-15 h40
  text "VCC_IO" at -604.07,-19.99 h40
  text "GND" at -718.37,-119.99 h40
  text "GND" at -69,-119.99 h40
  text ".BoardVersion" at -327.34,-199.22 h35 r270
  text "CSN" at -718.37,-219.99 h40
  text "A1" at -69,-220 h40
  text "SCK" at -718.37,-319.99 h40
  text "A2" at -69,-320 h40
  text "SDI" at -731.7,-419.99 h40
  text "B1" at -69,-420 h40
  text "SDO" at -718.37,-519.99 h40
  text "B2" at -69,-520 h40
  text "GND" at -718.37,-619.99 h40
  text "Max. current: IRMS = '.IRMS'" at -690.34,-619.34 h50 r270
  text "Supply range: VS = '.VS'" at -647.39,-619.34 h50 r270
  text "IC name: '.Chip'" at -608.34,-619.34 h50 r270
  text "GND" at -69,-619.99 h40
  text ".BoardName" at -271.28,-636.58 h35 r270
  text "CLK16" at -645.06,-719.99 h40
  text "AIN_REF" at -69,-719.99 h40
  text "DRV_ENN" at -558.42,-819.99 h40
  text "ENCA" at -69,-819.99 h40
  text "REFL" at -678.38,-919.99 h40
  text "ENCB" at -69,-919.99 h40
  text "REFR" at -678.38,-1019.99 h40
  text "ENCN" at -69,-1019.99 h40
TopAsm:
  text ".BoardVersion" at -793.16,-246.55 h40 r90
  text ".BoardName" at -793.16,-866.69 h40 r90

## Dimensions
-950,10.63 to 50,10.63 on Dimension
10.63,-1050 to 10.63,50 on Dimension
